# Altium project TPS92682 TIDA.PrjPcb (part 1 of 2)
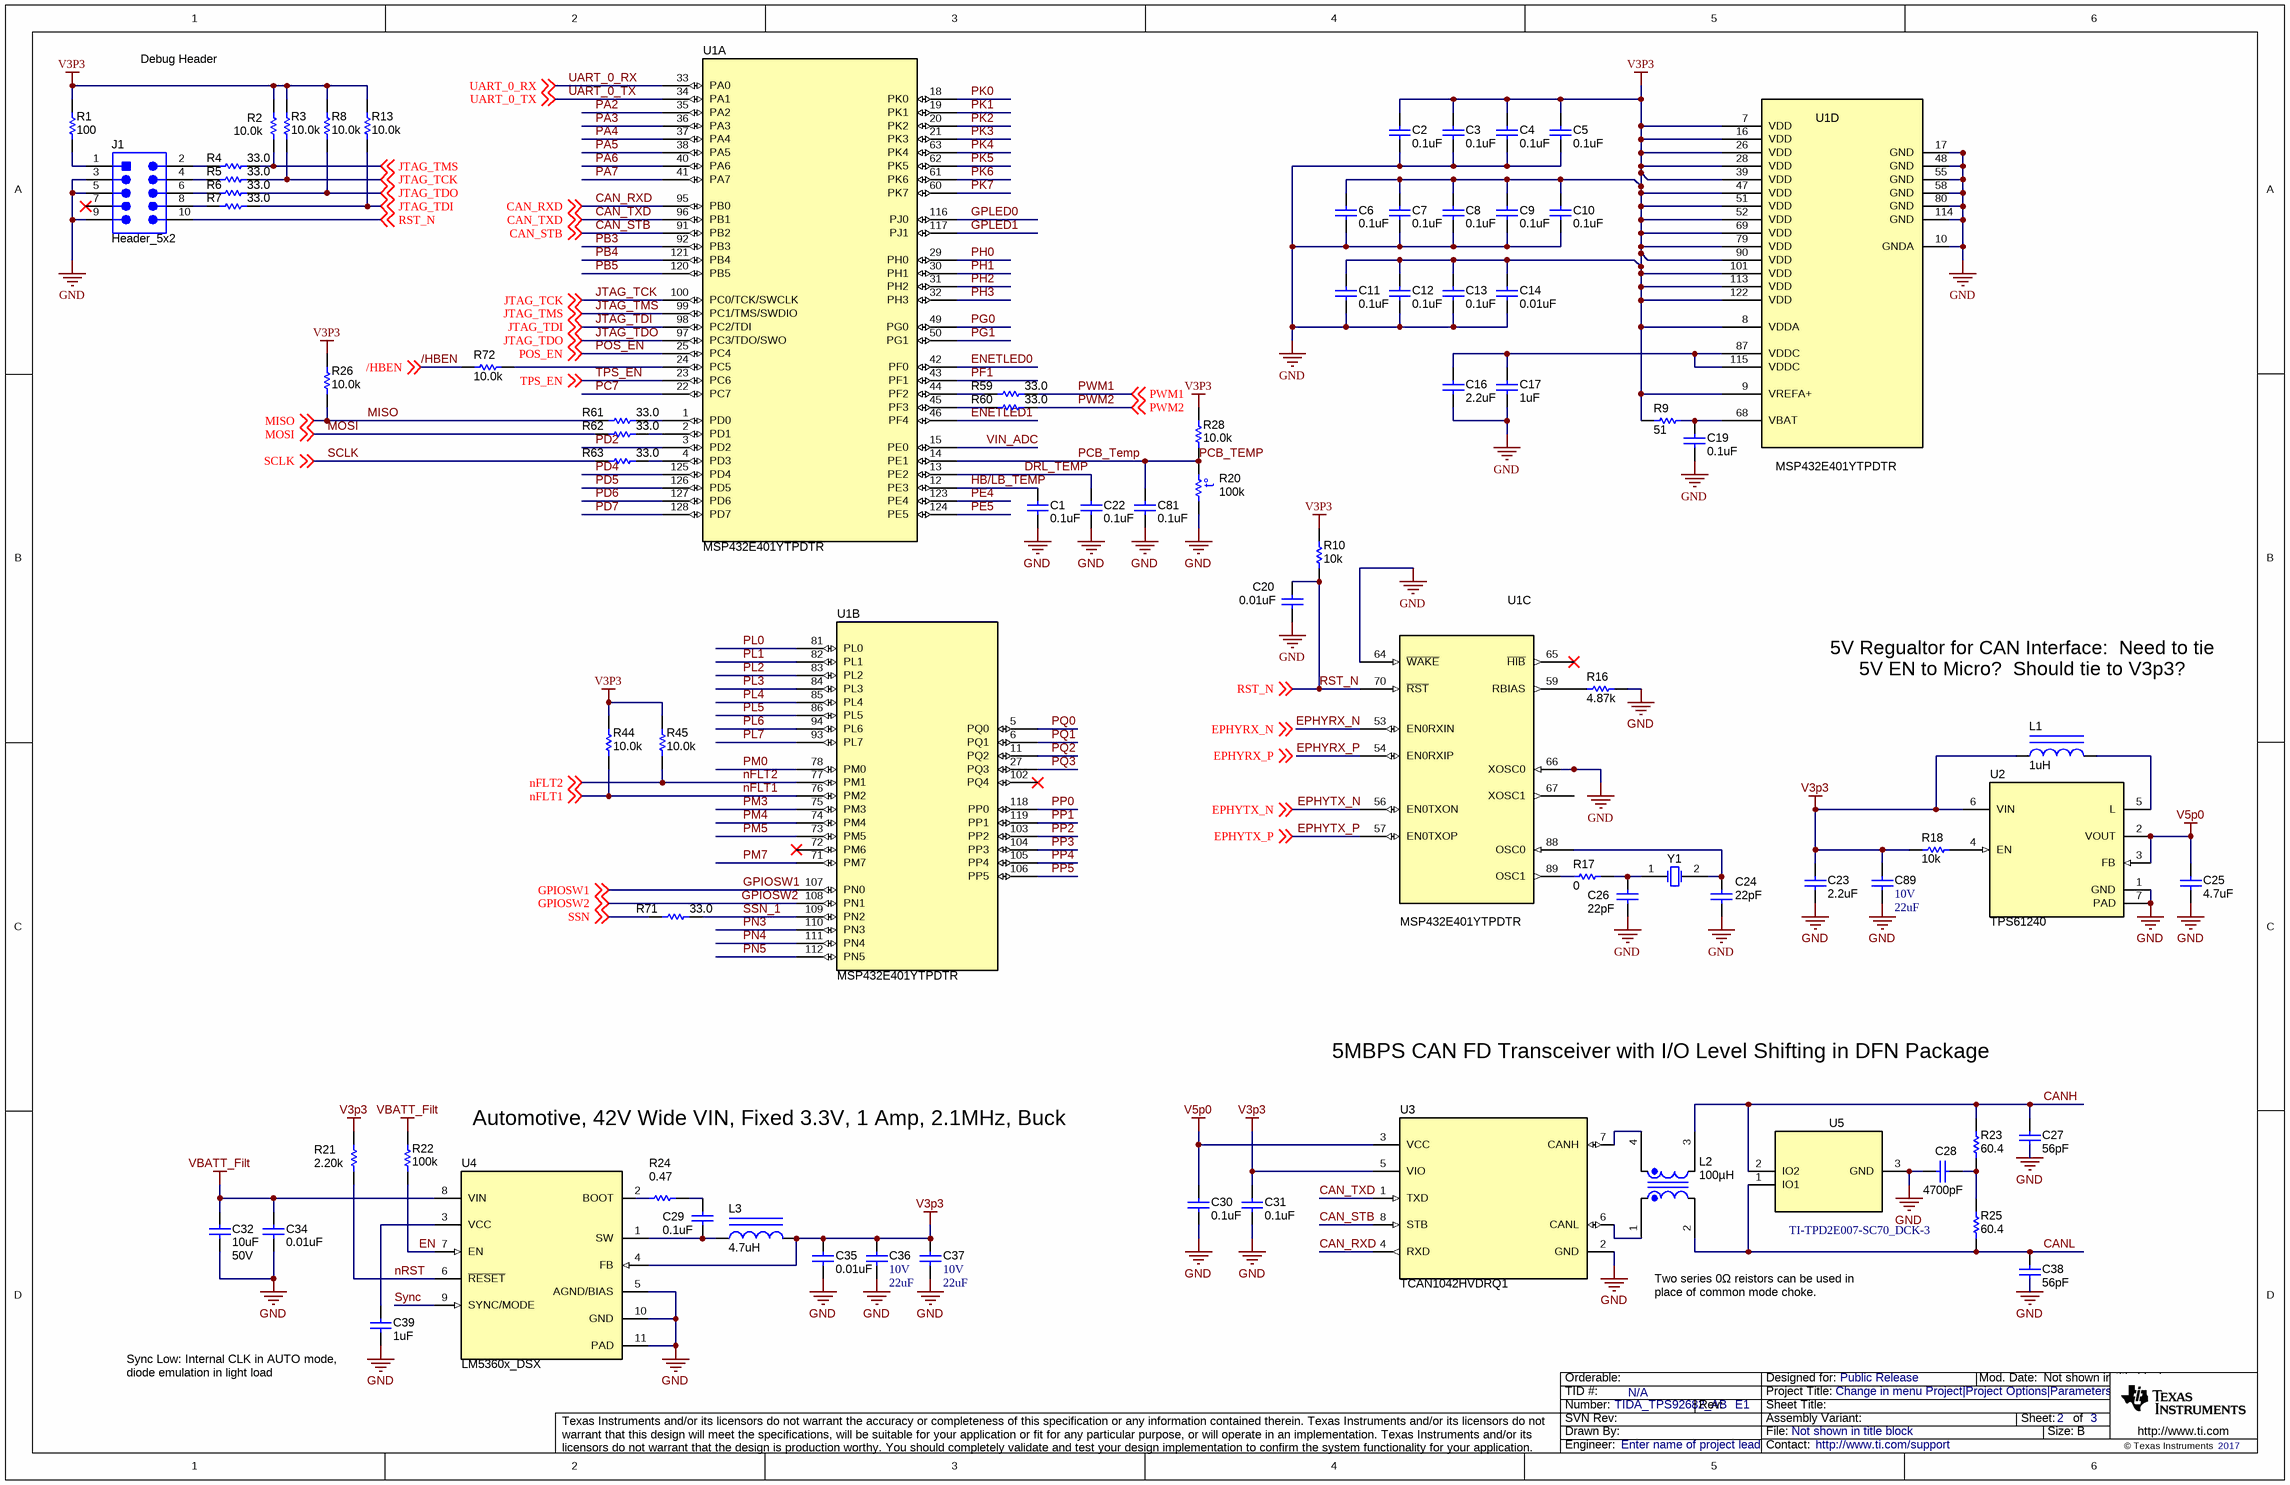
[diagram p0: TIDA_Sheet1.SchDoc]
CopyrightYear: 2017; PCB_Layout: Who did the Layout?; PCB_Rev: E1; PRJ_Customer: Public Release; PRJ_Engineer: Enter name of project lead; PRJ_Number: TIDA_TPS92682_AB; PRJ_Title: Change in menu Project|Project Options|Parameters; SCH_Rev: E1; TechSupport: http://www.ti.com/support; TID: N/A
3 sheets, 199 parts. Net scope: global (net labels, ports and power ports of the same name join across sheets).
Board file: TIDA TPS92682_AB.PcbDoc
Sheets:
  TIDA_Sheet1.SchDoc
  EVM_Hardware.SchDoc
  TIDA_Sheet2.SchDoc

## Sheet TIDA_Sheet1.SchDoc
size 431 x 279 mm; Date: Not shown in title block; ApprovedBy: Not shown in title block; CheckedBy: Not shown in title block; Author: Not shown in title block; CompanyName: Not shown in title block; Engineer: Not shown in title block; Organization: Not shown in title block; Address1: Not shown in title block; Address2: Not shown in title block; Address3: Not shown in title block; Address4: Not shown in title block; DocumentNumber: 1; Revision: Use project parameter SCH_Rev; SheetNumber: 2; SheetTotal: 3; PageSetup: Record=PageOptions¦CenterHorizontal=True¦CenterVertical=True¦PrintScale=1.00¦XCorrection=1.00¦YCorrection=1.00¦PrintKind=0¦BorderSize=5000000¦LeftOffset=0¦BottomOffset=0¦Orientation=2¦PaperLength=1000¦PaperWidth=1000¦Scale=100¦PaperSource=15¦PrintQuality=600¦MediaType=1¦DitherType=10¦PaperKind=Letter¦PrintScaleMode=1

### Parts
C1  ValueDisplayed: 0.1uF  [0402]  (hidden comment: CGA2B3X7R1H104M050BB)
C2  ValueDisplayed: 0.1uF  [0402]  (hidden comment: Capacitor)
C3  ValueDisplayed: 0.1uF  [0402]  (hidden comment: Capacitor)
C4  ValueDisplayed: 0.1uF  [0402]  (hidden comment: Capacitor)
C5  ValueDisplayed: 0.1uF  [0402]  (hidden comment: Capacitor)
C6  ValueDisplayed: 0.1uF  [0402]  (hidden comment: Capacitor)
C7  ValueDisplayed: 0.1uF  [0402]  (hidden comment: Capacitor)
C8  ValueDisplayed: 0.1uF  [0402]  (hidden comment: Capacitor)
C9  ValueDisplayed: 0.1uF  [0402]  (hidden comment: Capacitor)
C10  ValueDisplayed: 0.1uF  [0402]  (hidden comment: Capacitor)
C11  ValueDisplayed: 0.1uF  [0402]  (hidden comment: Capacitor)
C12  ValueDisplayed: 0.1uF  [0402]  (hidden comment: Capacitor)
C13  ValueDisplayed: 0.1uF  [0402]  (hidden comment: Capacitor)
C14  ValueDisplayed: 0.01uF  [0402]  (hidden comment: Capacitor)
C16  ValueDisplayed: 2.2uF  [0402]  (hidden comment: Capacitor)
C17  ValueDisplayed: 1uF  [0402]  (hidden comment: Capacitor)
C19  ValueDisplayed: 0.1uF  [0402]  (hidden comment: Capacitor)
C20  ValueDisplayed: 0.01uF  [0402]  (hidden comment: Capacitor)
C22  ValueDisplayed: 0.1uF  [0402]  (hidden comment: CGA2B3X7R1H104M050BB)
C23  ValueDisplayed: 2.2uF  [0603S]  (hidden comment: Capacitor)
C24  ValueDisplayed: 22pF  [0402]  (hidden comment: Capacitor)
C25  ValueDisplayed: 4.7uF  [0603S]  (hidden comment: Capacitor)
C26  ValueDisplayed: 22pF  [0402]  (hidden comment: Capacitor)
C27  ValueDisplayed: 56pF  [0603S]  (hidden comment: Capacitor)
C28  ValueDisplayed: 4700pF  [0603S]  (hidden comment: Capacitor)
C29  ValueDisplayed: 0.1uF  [0603S]  (hidden comment: Capacitor)
C30  ValueDisplayed: 0.1uF  [0603S]  (hidden comment: Capacitor)
C31  ValueDisplayed: 0.1uF  [0603S]  (hidden comment: Capacitor)
C32  ValueDisplayed: 10uF  VDC_V: 50V  [1210_280]  (hidden comment: CGA6P3X7S1H106K250AB)
C34  ValueDisplayed: 0.01uF  [0402]  (hidden comment: Capacitor)
C35  ValueDisplayed: 0.01uF  [0402S]  (hidden comment: Capacitor)
C36  VDC_V: 10V  ValueDisplayed: 22uF  [1206_180]  (hidden comment: GCM31CR71A226KE02)
C37  VDC_V: 10V  ValueDisplayed: 22uF  [1206_180]  (hidden comment: GCM31CR71A226KE02)
C38  ValueDisplayed: 56pF  [0603S]  (hidden comment: Capacitor)
C39  ValueDisplayed: 1uF  [0603S]  (hidden comment: Capacitor)
C81  ValueDisplayed: 0.1uF  [0402]  (hidden comment: CGA2B3X7R1H104M050BB)
C89  VDC_V: 10V  ValueDisplayed: 22uF  [1206_180]  (hidden comment: GCM31CR71A226KE02)
J1  Header_5x2  [Samtec_FTSH-105-01-x-DV]
L1  ValueDisplayed: 1uH  [NLCV32]  (hidden comment: Inductor_Iron)
L2  ValueDisplayed: 100µH  [SIMDAD_1812]  (hidden comment: INDUCTOR_COUPLED_12_43)
L3  ValueDisplayed: 4.7uH  [FDSD0420]  (hidden comment: FDSD0420D-4R7M)
R1  ValueDisplayed: 100  [0402]  (hidden comment: RMCF0402JT100R)
R2  ValueDisplayed: 10.0k  [0402]  (hidden comment: RMCF0402FT10K0)
R3  ValueDisplayed: 10.0k  [0402]  (hidden comment: RMCF0402FT10K0)
R4  ValueDisplayed: 33.0  [0402]  (hidden comment: RMCF0402FT33R0)
R5  ValueDisplayed: 33.0  [0402]  (hidden comment: RMCF0402FT33R0)
R6  ValueDisplayed: 33.0  [0402]  (hidden comment: RMCF0402FT33R0)
R7  ValueDisplayed: 33.0  [0402]  (hidden comment: RMCF0402FT33R0)
R8  ValueDisplayed: 10.0k  [0402]  (hidden comment: RMCF0402FT10K0)
R9  ValueDisplayed: 51  [0603]  (hidden comment: Resistor)
R10  ValueDisplayed: 10k  [0402]  (hidden comment: Resistor)
R13  ValueDisplayed: 10.0k  [0402]  (hidden comment: RMCF0402FT10K0)
R16  ValueDisplayed: 4.87k  [0402]  (hidden comment: ERA-2AEB4871X)
R17  ValueDisplayed: 0  [0402]  (hidden comment: Resistor)
R18  ValueDisplayed: 10k  [0402]  (hidden comment: Resistor)
R20  value 100k  [0603_HV]  (hidden comment: Thermistor)
R21  ValueDisplayed: 2.20k  [0603S]  (hidden comment: Resistor)
R22  ValueDisplayed: 100k  [0603_HV]  (hidden comment: Resistor)
R23  ValueDisplayed: 60.4  [1206]  (hidden comment: Resistor)
R24  ValueDisplayed: 0.47  [0402S]  (hidden comment: Resistor)
R25  ValueDisplayed: 60.4  [1206]  (hidden comment: Resistor)
R26  ValueDisplayed: 10.0k  [0402]  (hidden comment: RMCF0402FT10K0)
R28  ValueDisplayed: 10.0k  [0402]  (hidden comment: RMCF0402FT10K0)
R44  ValueDisplayed: 10.0k  [0402]  (hidden comment: RMCF0402FT10K0)
R45  ValueDisplayed: 10.0k  [0402]  (hidden comment: RMCF0402FT10K0)
R59  ValueDisplayed: 33.0  [0402]  (hidden comment: RMCF0402FT33R0)
R60  ValueDisplayed: 33.0  [0402]  (hidden comment: RMCF0402FT33R0)
R61  ValueDisplayed: 33.0  [0402]  (hidden comment: RMCF0402FT33R0)
R62  ValueDisplayed: 33.0  [0402]  (hidden comment: RMCF0402FT33R0)
R63  ValueDisplayed: 33.0  [0402]  (hidden comment: RMCF0402FT33R0)
R71  ValueDisplayed: 33.0  [0402]  (hidden comment: RMCF0402FT33R0)
R72  ValueDisplayed: 10.0k  [0402]  (hidden comment: RMCF0402FT10K0)
U1  MSP432E401YTPDTR  [PDT0128A]  (parts A,B,C,D of 4)
U2  TPS61240  [DRV0006A]
U3  TCAN1042HVDRQ1  [D0008A_L]
U4  LM5360x_DSX  [DSX0010A]
U5  TI-TPD2E007-SC70_DCK-3  [DCK0003A_N]
Y1  Xtal  [NDK_NX5032GA]  (value not drawn)

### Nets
GND: C1.2 C2.2 C3.2 C4.2 C5.2 C6.2 C7.2 C8.2 C9.2 C10.2 C11.2 C12.2 C13.2 C14.2 C16.2 C17.2 C19.2 C20.2 C22.2 C23.2 C24.2 C25.2 C26.2 C27.2 C28.2 C30.2 C31.2 C32.2 C34.2 C35.2 C36.2 C37.2 C38.2 C39.2 C81.2 C89.2 J1.3 J1.5 J1.9 R16.2 R20.1 U1.10(GNDA) U1.17(GND) U1.48(GND) U1.55(GND) U1.58(GND) U1.64(~{WAKE}) U1.66(XOSC0) U1.80(GND) U1.114(GND) U2.1(GND) U2.7(PAD) U3.2(GND) U4.5(AGND/BIAS) U4.10(GND) U4.11(PAD) U5.3(GND)
V3P3: C2.1 C3.1 C4.1 C5.1 C6.1 C7.1 C8.1 C9.1 C10.1 C11.1 C12.1 C13.1 C14.1 C23.1 C31.1 C35.1 C36.1 C37.1 C89.1 L1.1 L3.2 R1.2 R2.2 R3.2 R8.2 R9.1 R10.2 R13.2 R18.2 R21.1 R26.2 R28.2 R44.2 R45.2 U1.7(VDD) U1.8(VDDA) U1.9(VREFA+) U1.16(VDD) U1.26(VDD) U1.28(VDD) U1.39(VDD) U1.47(VDD) U1.51(VDD) U1.52(VDD) U1.69(VDD) U1.79(VDD) U1.90(VDD) U1.101(VDD) U1.113(VDD) U1.122(VDD) U2.6(VIN) U3.5(VIO) U4.4(FB)
V5p0: C25.1 C30.1 U2.2(VOUT) U2.3(FB) U3.3(VCC)
VBATT_Filt: C32.1 C34.1 R22.2 U4.8(VIN)
/HBEN: R72.2 ; off-sheet /HBEN
CAN_RXD: U1.95(PB0) U3.4(RXD) ; off-sheet CAN_RXD
CAN_STB: U1.91(PB2) U3.8(STB) ; off-sheet CAN_STB
CAN_TXD: U1.96(PB1) U3.1(TXD) ; off-sheet CAN_TXD
CANH: C27.1 L2.3 R23.2 U5.2(IO2)
CANL: C38.1 L2.2 R25.1 U5.1(IO1)
DRL_TEMP: C22.1 U1.13(PE2)
EN: R22.1 U4.7(EN)
ENETLED0: U1.42(PF0)
ENETLED1: U1.46(PF4)
EPHYRX_N: U1.53(EN0RXIN) ; off-sheet EPHYRX_N
EPHYRX_P: U1.54(EN0RXIP) ; off-sheet EPHYRX_P
EPHYTX_N: U1.56(EN0TXON) ; off-sheet EPHYTX_N
EPHYTX_P: U1.57(EN0TXOP) ; off-sheet EPHYTX_P
GPIOSW1: U1.107(PN0) ; off-sheet GPIOSW1
GPIOSW2: U1.108(PN1) ; off-sheet GPIOSW2
GPLED0: U1.116(PJ0)
GPLED1: U1.117(PJ1)
HB/LB_TEMP: C1.1 U1.12(PE3)
JTAG_TCK: R3.1 R5.2 U1.100(PC0/TCK/SWCLK) ; off-sheet JTAG_TCK
JTAG_TDI: R7.2 R13.1 U1.98(PC2/TDI) ; off-sheet JTAG_TDI
JTAG_TDO: R6.2 R8.1 U1.97(PC3/TDO/SWO) ; off-sheet JTAG_TDO
JTAG_TMS: R2.1 R4.2 U1.99(PC1/TMS/SWDIO) ; off-sheet JTAG_TMS
MISO: R26.1 R61.1 ; off-sheet MISO
MOSI: R62.1 ; off-sheet MOSI
nFLT1: R44.1 U1.76(PM2) ; off-sheet nFLT1
nFLT2: R45.1 U1.77(PM1) ; off-sheet nFLT2
nRST: R21.2 U4.6(~{RESET})
PA2: U1.35(PA2)
PA3: U1.36(PA3)
PA4: U1.37(PA4)
PA5: U1.38(PA5)
PA6: U1.40(PA6)
PA7: U1.41(PA7)
PB3: U1.92(PB3)
PB4: U1.121(PB4)
PB5: U1.120(PB5)
PC7: U1.22(PC7)
PCB_Temp: C81.1 R20.2 R28.1 U1.14(PE1)
PD2: U1.3(PD2)
PD4: U1.125(PD4)
PD5: U1.126(PD5)
PD6: U1.127(PD6)
PD7: U1.128(PD7)
PE4: U1.123(PE4)
PE5: U1.124(PE5)
PF1: U1.43(PF1)
PG0: U1.49(PG0)
PG1: U1.50(PG1)
PH0: U1.29(PH0)
PH1: U1.30(PH1)
PH2: U1.31(PH2)
PH3: U1.32(PH3)
PK0: U1.18(PK0)
PK1: U1.19(PK1)
PK2: U1.20(PK2)
PK3: U1.21(PK3)
PK4: U1.63(PK4)
PK5: U1.62(PK5)
PK6: U1.61(PK6)
PK7: U1.60(PK7)
PL0: U1.81(PL0)
PL1: U1.82(PL1)
PL2: U1.83(PL2)
PL3: U1.84(PL3)
PL4: U1.85(PL4)
PL5: U1.86(PL5)
PL6: U1.94(PL6)
PL7: U1.93(PL7)
PM0: U1.78(PM0)
PM3: U1.75(PM3)
PM4: U1.74(PM4)
PM5: U1.73(PM5)
PM7: U1.71(PM7)
PN3: U1.110(PN3)
PN4: U1.111(PN4)
PN5: U1.112(PN5)
POS_EN: U1.25(PC4) ; off-sheet POS_EN
PP0: U1.118(PP0)
PP1: U1.119(PP1)
PP2: U1.103(PP2)
PP3: U1.104(PP3)
PP4: U1.105(PP4)
PP5: U1.106(PP5)
PQ0: U1.5(PQ0)
PQ1: U1.6(PQ1)
PQ2: U1.11(PQ2)
PQ3: U1.27(PQ3)
PWM1: R59.2 ; off-sheet PWM1
PWM2: R60.2 ; off-sheet PWM2
RST_N: C20.1 J1.10 R10.1 U1.70(~{RST}) ; off-sheet RST_N
SCLK: R63.1 ; off-sheet SCLK
SSN: R71.1 ; off-sheet SSN
SSN_1: R71.2 U1.109(PN2)
Sync: U4.9(SYNC/MODE)
TPS_EN: U1.23(PC6) ; off-sheet TPS_EN
UART_0_RX: U1.33(PA0) ; off-sheet UART_0_RX
UART_0_TX: U1.34(PA1) ; off-sheet UART_0_TX
VIN_ADC: U1.15(PE0)
NetC16_1: C16.1 C17.1 U1.87(VDDC) U1.115(VDDC)
NetC19_1: C19.1 R9.2 U1.68(VBAT)
NetC24_1: C24.1 U1.88(OSC0) Y1.2(OSC2)
NetC26_1: C26.1 R17.2 Y1.1(OSC1)
NetC28_1: C28.1 R23.1 R25.2
NetC29_1: C29.1 R24.2
NetC29_2: C29.2 L3.1 U4.1(SW)
NetC39_1: C39.1 U4.3(VCC)
NetJ1_1: J1.1 R1.1
NetJ1_2: J1.2 R4.1
NetJ1_4: J1.4 R5.1
NetJ1_6: J1.6 R6.1
NetJ1_8: J1.8 R7.1
NetL1_2: L1.2 U2.5(L)
NetL2_1: L2.1 U3.6(CANL)
NetL2_4: L2.4 U3.7(CANH)
NetR16_1: R16.1 U1.59(RBIAS)
NetR17_1: R17.1 U1.89(OSC1)
NetR18_1: R18.1 U2.4(EN)
NetR24_1: R24.1 U4.2(BOOT)
NetR59_1: R59.1 U1.44(PF2)
NetR60_1: R60.1 U1.45(PF3)
NetR61_2: R61.2 U1.1(PD0)
NetR62_2: R62.2 U1.2(PD1)
NetR63_2: R63.2 U1.4(PD3)
NetR72_1: R72.1 U1.24(PC5)

Not connected (* = marked no-connect by the designer): J1 7*; U1 65(~{HIB})* 67(XOSC1) 72(PM6)* 102(PQ4)*

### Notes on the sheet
- Debug Header
- 5V Regualtor for CAN Interface:  Need to tie 5V EN to Micro?  Should tie to V3p3?
- 5MBPS CAN FD Transceiver with I/O Level Shifting in DFN Package
- Automotive, 42V Wide VIN, Fixed 3.3V, 1 Amp, 2.1MHz, Buck
- Two series 0Ω reistors can be used in
- place of common mode choke.
- diode emulation in light load
- (near C39) Sync Low: Internal CLK in AUTO mode,
- Labels drawn without touching a wire or pin: EPHYRX_N, EPHYRX_P

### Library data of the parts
C1 C22 C81 = CMP-0006326-2: CAP, CERM, 0.1 uF, 50 V, +/- 20%, X7R, AEC-Q200 Grade 1, 0402; Manufacturer: TDK; Polarized: N; CompType: Capacitor; Value: 0.1uF; U/M: EA; Cap_F: 100nF; Value1: Unknown; VDC_V: 50V; TaMin_C: -55°C; TaMax_C: 125°C; SizeArea_mm2: 0.5; SizeAreaWB_mm2: 3; SizeX_mm: 1; SizeZ_mm: 0.6; AEC Category: Q200; AEC Qualified: Y
C2-C13 C19 = CMP-0006641-2: CAP, CERM, 0.1 uF, 16 V, +/- 10%, X7R, 0402; PartNumber: GRM155R71C104KA88D; Manufacturer: MuRata; Polarized: N; Value: 0.1uF; U/M: EA; Cap_F: 100nF; Value1: Unknown; VDC_V: 16V; TaMin_C: -55°C; TaMax_C: 125°C; AEC Category: Q200; SizeArea_mm2: 0.5; SizeAreaWB_mm2: 3; SizeX_mm: 1; SizeZ_mm: 0.6
C14 C20 C34 = CMP-0006639-2: CAP, CERM, 0.01 uF, 16 V, +/- 10%, X7R, 0402; PartNumber: GRM155R71C103KA01D; Manufacturer: MuRata; Polarized: N; Value: 0.01uF; U/M: EA; Cap_F: 10nF; Value1: Unknown; VDC_V: 16V; TaMin_C: -55°C; TaMax_C: 125°C; AEC Category: Q200; SizeArea_mm2: 0.5; SizeAreaWB_mm2: 3; SizeX_mm: 1; SizeZ_mm: 0.6
C16 = CMP-0006594-2: CAP, CERM, 2.2 uF, 16 V, +/- 10%, X5R, 0402; PartNumber: GRM155R61C225KE11D; Manufacturer: MuRata; Polarized: N; Value: 2.2uF; U/M: EA; Cap_F: 2.2µF; Value1: Unknown; VDC_V: 16V; TaMin_C: -55°C; TaMax_C: 85°C; AEC Category: Q200; SizeArea_mm2: 0.5; SizeAreaWB_mm2: 3; SizeX_mm: 1; SizeZ_mm: 0.6
C17 = CMP-0006272-2: CAP, CERM, 1 uF, 16 V, +/- 10%, X5R, 0402; PartNumber: C1005X5R1C105K050BC; Manufacturer: TDK; Polarized: N; Value: 1uF; U/M: EA; Cap_F: 1µF; Value1: Unknown; VDC_V: 16V; TaMin_C: -55°C; TaMax_C: 85°C; AEC Category: Q200; SizeArea_mm2: 0.5; SizeAreaWB_mm2: 3; SizeX_mm: 1; SizeZ_mm: 0.6
C23 = CMP-0006906-5: CAP, CERM, 2.2 uF, 10 V, +/- 10%, X5R, 0603; PartNumber: C0603C225K8PACTU; Manufacturer: Kemet; Polarized: N; Value: 2.2uF; U/M: EA; Cap_F: 2.2µF; Value1: Unknown; VDC_V: 10V; TaMin_C: -55°C; TaMax_C: 85°C; Cap_Case: 0603; SizeArea_mm2: 1.28; SizeAreaWB_mm2: 4.68; SizeX_mm: 1.6; SizeY_mm: 0.8; SizeZ_mm: 1; AEC Category: Q200
C24 C26 = CMP-0006248-2: CAP, CERM, 22 pF, 50 V, +/- 5%, C0G/NP0, 0402; PartNumber: C1005C0G1H220J050BA; Manufacturer: TDK; Polarized: N; Value: 22pF; U/M: EA; Value1: Unknown; VDC_V: 50V; TaMin_C: -55°C; TaMax_C: 125°C; AEC Category: Q200; SizeArea_mm2: 0.5; SizeAreaWB_mm2: 3; SizeX_mm: 1; SizeZ_mm: 0.6
C25 = CMP-0006949-5: CAP, CERM, 4.7 uF, 10 V, +/- 10%, X5R, 0603; PartNumber: C0603C475K8PACTU; Manufacturer: Kemet; Polarized: N; Value: 4.7uF; U/M: EA; Cap_F: 4.7µF; ESR_ohm: 6m; Value1: 0.006 ohm; VDC_V: 10V; IRMS_A: 7.24A; TaMin_C: -55°C; TaMax_C: 85°C; Cap_Case: 0603; SizeArea_mm2: 1.28; SizeAreaWB_mm2: 4.68; SizeX_mm: 1.6; SizeY_mm: 0.8; SizeZ_mm: 1; AEC Category: Q200
C27 C38 = CMP-0007224-4: CAP, CERM, 56 pF, 50 V, +/- 5%, C0G/NP0, 0603; PartNumber: GRM1885C1H560JA01D; Manufacturer: MuRata; Polarized: N; Value: 56pF; U/M: EA; Value1: Unknown; VDC_V: 50V; TaMin_C: -55°C; TaMax_C: 125°C; Cap_Case: 0603; SizeArea_mm2: 1.28; SizeAreaWB_mm2: 4.68; SizeX_mm: 1.6; SizeY_mm: 0.8; SizeZ_mm: 1; AEC Category: Q200
C28 = CMP-0007146-4: CAP, CERM, 4700 pF, 50 V, +/- 10%, X7R, AEC-Q200 Grade 1, 0603; PartNumber: GCM188R71H472KA37D; Manufacturer: MuRata; Polarized: N; Value: 4700pF; U/M: EA; Cap_F: 4.7nF; Value1: Unknown; VDC_V: 50V; TaMin_C: -55°C; TaMax_C: 125°C; Cap_Case: 0603; SizeArea_mm2: 1.28; SizeAreaWB_mm2: 4.68; SizeX_mm: 1.6; SizeY_mm: 0.8; SizeZ_mm: 1; AEC Category: Q200; AEC Qualified: Y
C29 = CMP-0007144-4: CAP, CERM, 0.1 uF, 50 V, +/- 10%, X7R, 0603; PartNumber: GCM188R71H104KA57D; Manufacturer: MuRata; Polarized: N; Value: 0.1uF; U/M: EA; Cap_F: 100nF; ESR_ohm: 0.02; Value1: 0.02 ohm; VDC_V: 50V; IRMS_A: 1.84A; TaMin_C: -55°C; TaMax_C: 125°C; Cap_Case: 0603; SizeArea_mm2: 1.28; SizeAreaWB_mm2: 4.68; SizeX_mm: 1.6; SizeY_mm: 0.8; SizeZ_mm: 1; AEC Category: Q200
C30 C31 = CMP-0006752-5: CAP, CERM, 0.1 uF, 25 V, +/- 5%, X7R, 0603; PartNumber: 06033C104JAT2A; Manufacturer: AVX; Polarized: N; Value: 0.1uF; U/M: EA; Cap_F: 100nF; ESR_ohm: 0.05; Value1: 0.05 ohm; VDC_V: 25V; TaMin_C: -55°C; TaMax_C: 125°C; Cap_Case: 0603; SizeArea_mm2: 1.28; SizeAreaWB_mm2: 4.68; SizeX_mm: 1.6; SizeY_mm: 0.8; SizeZ_mm: 1; AEC Category: Q200
C32 = CMP-0009164-2: CAP, CERM, 10 uF, 50 V, +/- 10%, X7S, AEC-Q200 Grade 1, 1210; Manufacturer: TDK; Polarized: N; Value: 10uF; U/M: EA; Cap_F: 10µF; ESR_ohm: 2.827m; Value1: 0.002827 ohm; IRMS_A: 4.37286A; TaMin_C: -55°C; TaMax_C: 125°C; SizeArea_mm2: 8; SizeAreaWB_mm2: 14.7; SizeX_mm: 3.2; SizeY_mm: 2.5; SizeZ_mm: 2.8; AEC Category: Q200; AEC Qualified: Y; AEC Grade: 1
C35 = CMP-0006292-2: CAP, CERM, 0.01 uF, 16 V, +/- 10%, X7R, 0402; PartNumber: C1005X7R1C103K050BA; Manufacturer: TDK; Polarized: N; Value: 0.01uF; U/M: EA; Cap_F: 10nF; ESR_ohm: 0.0623; Value1: 0.0623 ohm; VDC_V: 16V; TaMin_C: -55°C; TaMax_C: 125°C; Cap_Case: 0402; SizeArea_mm2: 0.5; SizeAreaWB_mm2: 3; SizeX_mm: 1; SizeZ_mm: 0.6; AEC Category: Q200
C36 C37 C89 = CMP-0008811-2: CAP, CERM, 22 uF, 10 V, +/- 10%, X7R, AEC-Q200 Grade 1, 1206; Manufacturer: MuRata; TaMin_C: -55°C; Polarized: N; SizeAreaWB_mm2: 10.92; Value1: Unknown; U/M: EA; Value: 22uF; TaMax_C: 125°C; SizeZ_mm: 1.8; SizeX_mm: 3.2; SizeY_mm: 1.6; Cap_Case: 1206; SizeArea_mm2: 5.12; AEC Qualified: Y; Cap_F: 22µF; AEC Grade: 1; AEC Category: Q200
C39 = CMP-0007136-5: CAP, CERM, 1 uF, 16 V, +/- 10%, X7R, AEC-Q200 Grade 1, 0603; PartNumber: GCM188R71C105KA64D; Manufacturer: MuRata; Polarized: N; Value: 1uF; U/M: EA; Cap_F: 1µF; Value1: Unknown; VDC_V: 16V; TaMin_C: -55°C; TaMax_C: 125°C; Cap_Case: 0603; SizeArea_mm2: 1.28; SizeAreaWB_mm2: 4.68; SizeX_mm: 1.6; SizeY_mm: 0.8; SizeZ_mm: 1; AEC Category: Q200; AEC Qualified: Y
J1 = CMP-0075629-2: Header, 1.27mm, 5x2, Gold, Black, SMT; PartNumber: FTSH-105-01-F-DV; Manufacturer: Samtec; Pitch_mm: 1.27; Gender: Male; Row_Count: 2; Current_A: 3.3A; Cert_CSA: Y
L1 = CMP-0062763-1: Inductor, Wirewound, Ferrite, 1 uH, 1 A, 0.06 ohm, SMD; PartNumber: NLCV32T-1R0M-PF; Manufacturer: TDK; Value: 1uH; Ind_H: 1µH; Imax_A: 1A; Irms: 1A @ 20C rise; Isat: 1A @ 10% inductance drop; DCR_ohm: 0.06; SizeAreaWB_mm2: 13.44; SizeArea_mm2: 7.04; SizeX_mm: 3.2; SizeY_mm: 2.2; SizeZ_mm: 2.5; AEC Category: Q200; Green_Lifecycle: Active; Green_REACh: Passed
L2 = CMP-0076842-1: Coupled inductor, 100 µH, 0.15 A, 1.5 ohm, SMD; PartNumber: B82789C0104H001; Manufacturer: TDK; Value: 100uH; DCR_ohm: 1.5; AEC Category: Q200
L3 = CMP-0058987-1: Inductor, Shielded, 4.7 uH, 2.7 A, 0.083 ohm, AEC-Q200 Grade 1, SMD; Manufacturer: MuRata Toko; Isat: 2.7A @ 30% inductance drop; Irms: 3.6A @ 40C rise; SizeAreaWB_mm2: 27.04; DCR_ohm: 0.083; Value: 4.7uH; Imax_A: 2.7A; SizeZ_mm: 2; SizeX_mm: 4.2; SizeArea_mm2: 17.64; Ind_H: 4.7µH; AEC Qualified: Y; AEC Grade: 1; AEC Category: Q200
R1 = CMP-0026763-1: RES, 100, 1%, 0.063 W, AEC-Q200 Grade 0, 0402; Manufacturer: Stackpole Electronics Inc; Power_W: 63mW; TempCo: 100 ppm/C; Value_Code: 100R; U/M: EA; Value: 100; EIA_Code: E96; SizeX_mm: 1; SizeY_mm: 0.5; SizeZ_mm: 0.6; Value2: 0.063W; AEC Qualified: Y; AEC Grade: 0; AEC Category: Q200
R2 R3 R8 R13 R26 R28 R44 R45 R72 = CMP-0026754-1: RES, 10.0 k, 1%, 0.063 W, AEC-Q200 Grade 0, 0402; Manufacturer: Stackpole Electronics Inc; Power_W: 63mW; TempCo: 100 ppm/C; Value_Code: 10k0; U/M: EA; Value: 10.0k; EIA_Code: E96; Res_ohm: 10k; SizeX_mm: 1; SizeY_mm: 0.5; SizeZ_mm: 0.6; Value2: 0.063W; AEC Qualified: Y; VDC_V: 50V; AEC Grade: 0; AEC Category: Q200
R4-R7 R59-R63 R71 = CMP-0026759-1: RES, 33.0, 1%, 0.063 W, AEC-Q200 Grade 0, 0402; Manufacturer: Stackpole Electronics Inc; Power_W: 63mW; TempCo: 100 ppm/C; Value_Code: 33R0; U/M: EA; Value: 33.0; Res_ohm: 33; SizeX_mm: 1; SizeY_mm: 0.5; SizeZ_mm: 0.6; Value2: 0.063W; AEC Qualified: Y; VDC_V: 50V; AEC Grade: 0; AEC Category: Q200
R9 = CMP-0025825-4: RES, 51, 5%, 0.1 W, AEC-Q200 Grade 0, 0603; PartNumber: CRCW060351R0JNEA; Manufacturer: Vishay-Dale; Value: 51; Value_Code: 51R0; Power_W: 100mW; Value2: 0.1W; VDC_V: 75V; TempCo: 200 ppm/C; EIA_Code: E24; AEC Category: Q200; AEC Qualified: Y; AEC Grade: 0; SizeArea_mm2: 1.28; SizeX_mm: 1.6; SizeY_mm: 0.8; SizeZ_mm: 1
R10 R18 = CMP-0026825-5: RES, 10 k, 5%, 0.063 W, AEC-Q200 Grade 0, 0402; PartNumber: CRCW040210K0JNED; Manufacturer: Vishay-Dale; Value: 10k; Value_Code: 10k0; Power_W: 63mW; Value2: 0.063W; VDC_V: 50V; TempCo: 200 ppm/C; EIA_Code: E24; AEC Category: Q200; AEC Qualified: Y; AEC Grade: 0; SizeArea_mm2: 0.5; SizeX_mm: 1; SizeZ_mm: 0.6
R16 = CMP-0026781-1: RES, 4.87 k, 0.1%, 0.062 W, AEC-Q200 Grade 0, 0402; Manufacturer: Panasonic; Power_W: 62mW; TempCo: 25 ppm/C; Value_Code: 4k87; U/M: EA; Value: 4.87k; EIA_Code: E192; SizeX_mm: 1; SizeY_mm: 0.5; SizeZ_mm: 0.6; Value2: 0.062W; AEC Qualified: Y; VDC_V: 25V; AEC Grade: 0; AEC Category: Q200
R17 = CMP-0026992-3: RES, 0, 5%, 0.1 W, AEC-Q200 Grade 0, 0402; PartNumber: ERJ-2GE0R00X; Manufacturer: Panasonic; Value: 0; Value_Code: 0000; Power_W: 100mW; Value2: 0.1W; VDC_V: 50V; TempCo: 600 ppm/C; EIA_Code: E24; AEC Category: Q200; AEC Qualified: Y; SizeArea_mm2: 0.5; SizeAreaWB_mm2: 3; SizeX_mm: 1; SizeZ_mm: 0.6
R20 = CMP-0002354-3: Thermistor NTC, 100k ohm, 1%, 0603; PartNumber: NTCG164KF104F; Manufacturer: TDK; U/M: EA; TaMin_C: -40°C; TaMax_C: 125°C; SizeArea_mm2: 1.28; SizeAreaWB_mm2: 4.68; SizeX_mm: 1.6; SizeY_mm: 0.8; SizeZ_mm: 1
R21 = CMP-0022986-5: RES, 2.20 k, 1%, 0.1 W, 0603; PartNumber: RC0603FR-072K2L; Manufacturer: Yageo; Value: 2.20k; Res_ohm: 2.2k; Value_Code: 2k20; Power_W: 100mW; Value2: 0.1W; VDC_V: 75V; TempCo: 100 ppm/C; SizeArea_mm2: 1.28; SizeX_mm: 1.6; SizeY_mm: 0.8; SizeZ_mm: 1; AEC Category: Q200; AEC Qualified: N; SizeAreaWB_mm2: 4.68
R22 = CMP-0021990-4: RES, 100 k, 1%, 0.1 W, AEC-Q200 Grade 0, 0603; PartNumber: CRCW0603100KFKEA; Manufacturer: Vishay-Dale; Value: 100k; Power_W: 100mW; Value2: 0.1W; VDC_V: 75V; TempCo: 100 ppm/C; EIA_Code: E96; AEC Category: Q200; AEC Grade: 0; AEC Qualified: Y; SizeArea_mm2: 1.28; SizeX_mm: 1.6; SizeY_mm: 0.8; SizeZ_mm: 1
R23 R25 = CMP-0017102-3: RES, 60.4, 1%, 0.25 W, AEC-Q200 Grade 0, 1206; PartNumber: CRCW120660R4FKEA; Manufacturer: Vishay-Dale; Value: 60.4; Value_Code: 60R4; Power_W: 250mW; Value2: 0.25W; VDC_V: 200V; TempCo: 100 ppm/C; SizeArea_mm2: 5.12; SizeX_mm: 3.2; SizeY_mm: 1.6; SizeZ_mm: 1.35; EIA_Code: E96; AEC Category: Q200; AEC Qualified: Y; AEC Grade: 0
R24 = CMP-0026639-2: RES, 0.47, 1%, 0.125 W, AEC-Q200 Grade 0, 0402; PartNumber: ERJ-2BQFR47X; Manufacturer: Panasonic; Value: 0.47; Res_ohm: 4.7d; Value_Code: R470; Power_W: 125mW; Value2: 0.125W; TempCo: 250 ppm/C; SizeArea_mm2: 0.5; SizeX_mm: 1; SizeZ_mm: 0.6; EIA_Code: E96; AEC Category: Q200; AEC Qualified: Y; AEC Grade: 0; SizeAreaWB_mm2: 3
U1 = CMP-0077954-1: MSP432E401YTPDT, PDT0128A (TQFP-128); Alternate Manufacturer: Texas Instruments; SizeAreaWB_mm2: 324; SizeZ_mm: 1.2; SizeX_mm: 16; SizeArea_mm2: 256; CompType: IC; AEC Qualified: N; AEC Category: Q200
U2 = CMP-0067210-5: Automotive Catalog 5V, 400mA, 4MHz Step-Up DC/DC Converter, DRV0006A (WSON-6); PartNumber: TPS61240IDRVRQ1; Manufacturer: Texas Instruments; SizeArea_mm2: 4; SizeAreaWB_mm2: 9; SizeX_mm: 2; SizeZ_mm: 0.8; CompType: IC; U/M: EA
U3 = CMP-0075993-1: Automotive Fault Protected CAN Transceiver With Flexible Data-Rate, D0008A (SOIC-8); Manufacturer: Texas Instruments; Alternate PartNumber: TCAN1042HVDQ1; SizeAreaWB_mm2: 56.58; SizeArea_mm2: 30.38; SizeZ_mm: 1.75; SizeY_mm: 6.2; U/M: EA; CompType: IC; SizeX_mm: 4.9
U4 = CMP-0076338-3: 3.5V to 36V, 1A Synchronous 2.1MHz Step-Down Converter for Automotive Applications, DSX0010A (WSON-10); PartNumber: LM53601NQDSXRQ1; Manufacturer: Texas Instruments; SizeArea_mm2: 9.0; SizeAreaWB_mm2: 16.0; SizeX_mm: 3.0; SizeZ_mm: 0.8; CompType: IC; AEC Category: Q200; AEC Qualified: Y
U5 = CMP-0043100-2: ESD Protection Array for AC Signal Data Interface, 2 Channels, -40 to +85 degC, 3-pin SC70 (DCK), Green (RoHS & no Sb/Br); Manufacturer: Texas Instruments; PartNumber: TPD2E007DCKR; Breakdown Voltage(Min)(V): +/-14; IEC 61000-4-2 Air-Gap(+/- kV): 15; IEC 61000-4-2 Contact(+/- kV): 8; IO Leakage Current(nA): 50; SubFamily: ESD Solution; AEC Category: Q200; AEC Qualified: N; CompType: IC; SizeArea_mm2: 4.2; SizeAreaWB_mm2: 9.3; SizeX_mm: 2.1; SizeY_mm: 2; SizeZ_mm: 1.1
Y1 = CMP-0004665-3: Crystal, 25 MHz,  SMD; PartNumber: NX5032GA-25.000M-STD-CSK-4; Manufacturer: NDK; TaMin_C: -40°C; TaMax_C: 150°C; Frequency Stability: +/-30ppm; Frequency_Fixed: 25MHz

## Sheet EVM_Hardware.SchDoc
size 431 x 279 mm; Date: Not shown in title block; ApprovedBy: Not shown in title block; CheckedBy: Not shown in title block; Author: Not shown in title block; CompanyName: Not shown in title block; Engineer: Not shown in title block; Organization: Not shown in title block; Address1: Not shown in title block; Address2: Not shown in title block; Address3: Not shown in title block; Address4: Not shown in title block; DocumentNumber: 1; Revision: Use project parameter SCH_Rev; SheetNumber: 3; SheetTotal: 3; PageSetup: Record=PageOptions¦CenterHorizontal=True¦CenterVertical=True¦PrintScale=1.00¦XCorrection=1.00¦YCorrection=1.00¦PrintKind=0¦BorderSize=5000000¦LeftOffset=0¦BottomOffset=0¦Orientation=2¦PaperLength=1000¦PaperWidth=1000¦Scale=100¦PaperSource=15¦PrintQuality=600¦MediaType=1¦DitherType=10¦PaperKind=Letter¦PrintScaleMode=1
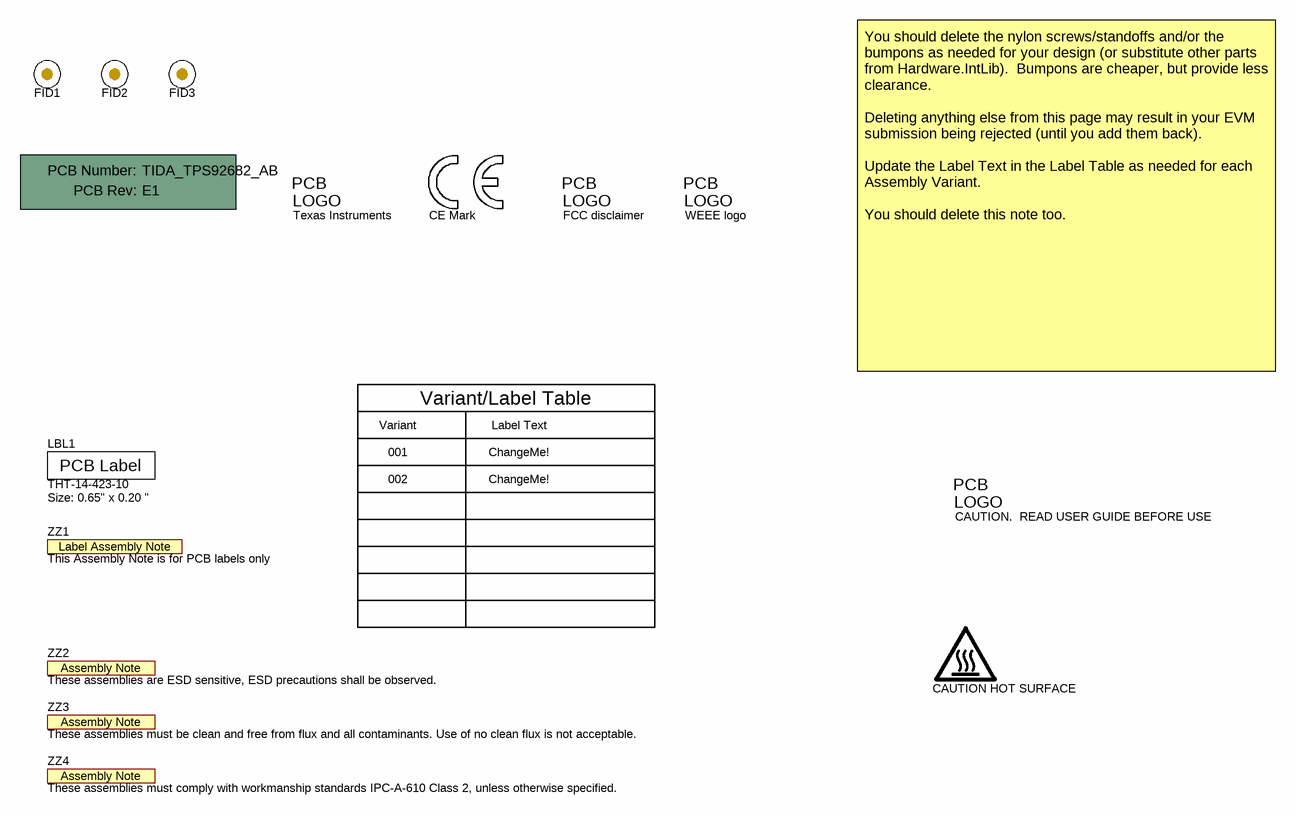
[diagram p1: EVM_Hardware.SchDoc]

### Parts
!PCB1  Printed Circuit Board  (value not drawn)  (mechanical)
FID1  Fiducial  [Fiducial10-20]  (value not drawn)
FID2  Fiducial  [Fiducial10-20]  (value not drawn)
FID3  Fiducial  [Fiducial10-20]  (value not drawn)
LBL1  THT-14-423-10  Note: Size: 0.65" x 0.20 "  [Label_650x200]
Logo1  CE Mark  [CE_Mark_5mm]  (no BOM)
Logo2  Texas Instruments  [TI_Stacked_Overlay_Small]  (no BOM)
Logo3  FCC disclaimer  [FCC_disclaimer]  (no BOM)
Logo4  WEEE logo  [WEEE_Minimum]  (no BOM)
Logo5  CAUTION.  READ USER GUIDE BEFORE USE  [IEC_Caution_Small]  (no BOM)
LOGO6  CAUTION HOT SURFACE  [IEC_HotSurface_Small]  (no BOM)
ZZ1  This Assembly Note is for PCB labels only  [AssemblyNoteLabel]  (no BOM)
ZZ2  These assemblies are ESD sensitive, ESD precautions shall be observed.  [AssemblyNote]  (no BOM)
ZZ3  These assemblies must be clean and free from flux and all contaminants. Use of no clean flux is not acceptable.  [AssemblyNote]  (no BOM)
ZZ4  These assemblies must comply with workmanship standards IPC-A-610 Class 2, unless otherwise specified.  [AssemblyNote]  (no BOM)

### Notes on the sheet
- Variant
- Variant/Label Table
- Label Text
- You should delete the nylon screws/standoffs and/or the bumpons as needed for your design (or substitute other parts from Hardware.IntLib).  Bumpons are cheaper, but provide less clearance.
  Deleting anything else from this page may result in your EVM submission being rejected (until you add them back).
  Update the Label Text in the Label Table as needed for each Assembly Variant.
  You should delete this note too.
- 001
- 002
- ChangeMe!

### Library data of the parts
!PCB1 = CMP-0003618-2: Manufacturer: Any; PartNumber: TIDA_TPS92682_AB
FID1-FID3 = CMP-0077181-1: Fiducial mark.  There is nothing to buy or mount.
LBL1 = CMP-0003625-1: Thermal Transfer Printable Labels, 0.650" W x 0.200" H - 10,000 per roll; Manufacturer: Brady; CompType: Label
Logo1 = CMP-0074844-1: SymbolCreator: a0412235
Logo2 = CMP-0074838-1: Texas Instrument Corporate Signature; SymbolCreator: a0412235; Lib Reference: TI_Logo; Library Reference: Logo
Logo3 = CMP-0074847-1: FCC_disclaimer; Library Reference: Logo
Logo4 = CMP-0074769-1
Logo5 = CMP-0074836-1: IEC 61010-1 Caution Warning; SymbolCreator: a0412235; Lib Reference: IEC_Caution
LOGO6 = CMP-0074837-1: IEC 61010-1 Hot Surface Warning; SymbolCreator: a0412235
ZZ1 = CMP-0003616-3
ZZ2 = CMP-0077236-1
ZZ3 = CMP-0077237-1
ZZ4 = CMP-0077238-1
